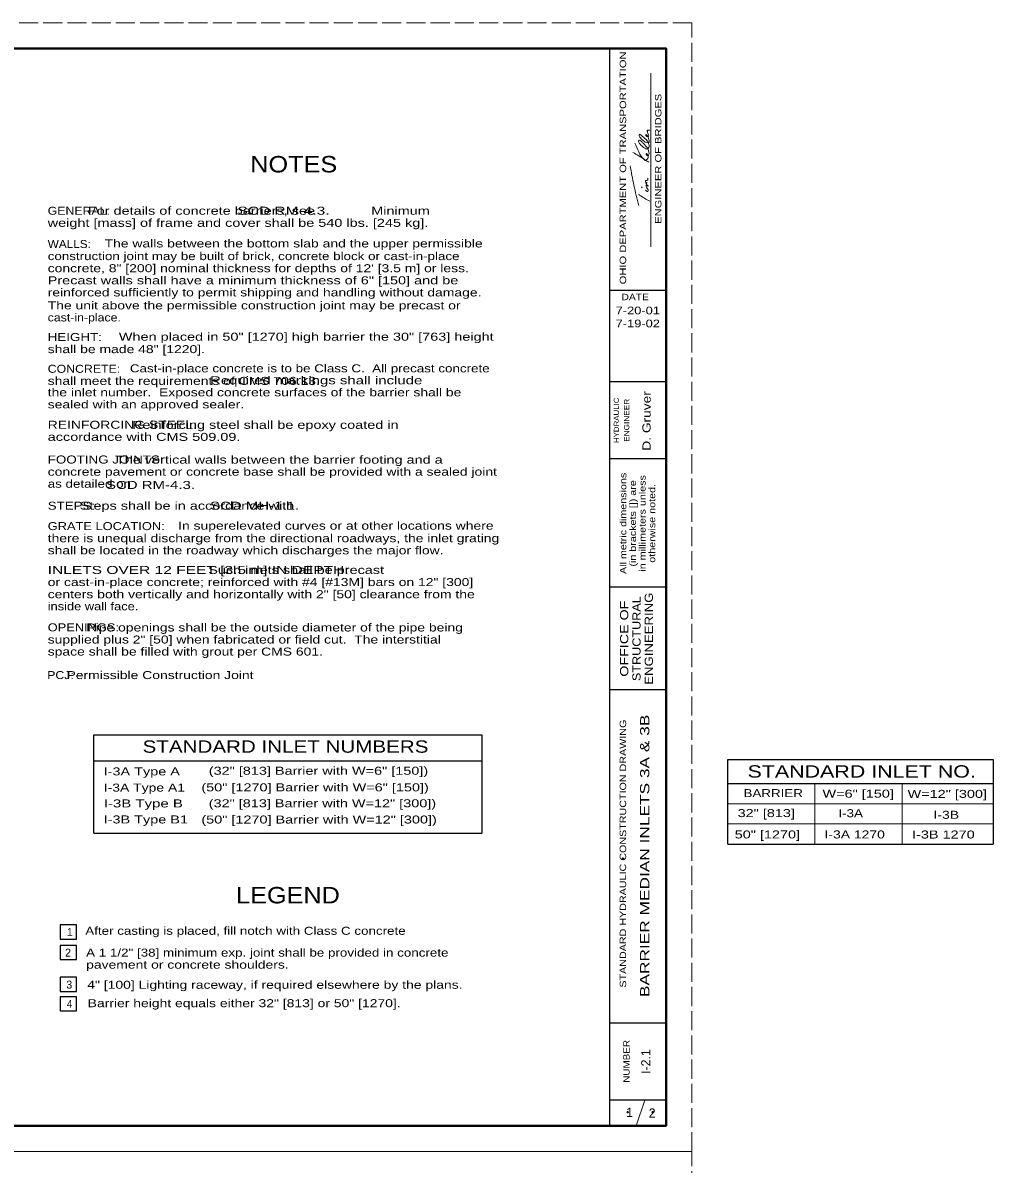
# Model space of a CAD drawing. Extents: x 1083.1 to 1123, y 697.4 to 741.4.
# Drawn here: x 1104.08 to 1123, y 719.1 to 741.35 of the extents above; entities that cross this region are included whole.
import ezdxf
from ezdxf.enums import TextEntityAlignment as Align

# ---------------------------------------------------------------- set-up
doc = ezdxf.new("R2010")
doc.units = 0
doc.header["$LTSCALE"] = 0.062
doc.header["$PDMODE"] = 32
doc.header["$PDSIZE"] = 0.031
doc.linetypes.add('LONG_DASHED', pattern=[7.5, 6, -1.5])
doc.layers.add('1', color=7, linetype='Continuous', lineweight=13)

msp = doc.modelspace()

# ---------------------------------------------------------------- linework, layer by layer
at = {"layer": '1', "lineweight": 25}
for p, q in [((1085.12642, 740.85408), (1116.62642, 740.85408)), ((1115.52642, 719.85408), (1115.52642, 740.85408)), ((1116.62642, 740.85408), (1116.62642, 719.85408)), ((1116.62642, 736.13825), (1115.52642, 736.13825)), ((1116.62642, 734.35408), (1115.52642, 734.35408)), ((1116.62642, 732.85408), (1115.52642, 732.85408)), ((1116.62642, 730.35408), (1115.52642, 730.35408)), ((1116.62642, 728.35408), (1115.52642, 728.35408)), ((1113.03458, 727.47617), (1113.03458, 725.559)), ((1105.465, 726.96483), (1113.03458, 726.96483)), ((1117.82975, 726.995), (1123.0025, 726.995)), ((1117.82975, 725.343), (1117.82975, 726.995)), ((1123.0025, 726.995), (1123.0025, 725.343)), ((1117.82975, 726.523), (1123.0025, 726.523)), ((1105.465, 725.559), (1113.03458, 725.559)), ((1117.82975, 725.343), (1123.0025, 725.343)), ((1116.62642, 721.85408), (1115.52642, 721.85408)), ((1116.62642, 720.35408), (1115.52642, 720.35408))]:
    msp.add_line(p, q, dxfattribs=at)
at = {"layer": '1'}
for p, q in [((1116.32517, 736.98508), (1116.32517, 740.37517)), ((1116.15767, 738.136), (1116.1475, 738.15525)), ((1119.52775, 726.523), (1119.52775, 725.343)), ((1121.22583, 726.523), (1121.22583, 725.343)), ((1117.82975, 726.12967), (1123.0025, 726.12967)), ((1117.82975, 725.73633), (1123.0025, 725.73633)), ((1116.04308, 719.85408), (1116.20975, 720.35408))]:
    msp.add_line(p, q, dxfattribs=at)
at = {"layer": '1', "linetype": 'LONG_DASHED'}
for points in [[(1083.12642, 719.35408), (1117.12642, 719.35408), (1117.12642, 741.35408), (1083.12642, 741.35408)], [(1083.12642, 697.35408), (1117.12642, 697.35408), (1117.12642, 719.35408), (1083.12642, 719.35408)]]:
    msp.add_lwpolyline(points, close=True, dxfattribs=at)
at = {"layer": '1', "lineweight": 25}
for points in [[(1116.62642, 719.85408), (1085.12642, 719.85408), (1085.12642, 740.85408)], [(1105.465, 725.559), (1105.465, 727.47617), (1113.03458, 727.47617)]]:
    msp.add_lwpolyline(points, dxfattribs=at)
at = {"layer": '1', "lineweight": 40}
msp.add_lwpolyline([(1085.12642, 740.85408), (1116.62642, 740.85408), (1116.62642, 719.85408), (1085.12642, 719.85408)], close=True, dxfattribs=at)
at = {"layer": '1', "lineweight": 25}
for points in [[(1104.81317, 723.76742), (1104.81317, 723.49208), (1105.1275, 723.49208), (1105.1275, 723.76742)], [(1104.81317, 723.36892), (1104.81317, 723.09342), (1105.1275, 723.09342), (1105.1275, 723.36892)], [(1104.81317, 722.74675), (1104.81317, 722.47125), (1105.1275, 722.47125), (1105.1275, 722.74675)], [(1104.81317, 722.36758), (1104.81317, 722.09225), (1105.1275, 722.09225), (1105.1275, 722.36758)]]:
    msp.add_lwpolyline(points, close=True, dxfattribs=at)
at = {"layer": '1'}
for points in [[(1116.01825, 739.01108), (1116.20142, 738.68275), (1116.21658, 738.67217), (1116.22675, 738.67217), (1116.25867, 738.69583), (1116.27375, 738.73), (1116.26875, 738.78125), (1116.25183, 738.80308), (1116.23833, 738.80308), (1116.23658, 738.79008), (1116.24675, 738.77492), (1116.26025, 738.7665), (1116.27533, 738.7665), (1116.2905, 738.78808), (1116.29392, 738.80742), (1116.28367, 738.86275), (1116.20142, 738.98317), (1116.15592, 739.02783), (1116.119, 739.06242), (1116.09383, 739.06458), (1116.09558, 739.026), (1116.12075, 738.98725), (1116.188, 738.92492), (1116.23008, 738.8995), (1116.26375, 738.895), (1116.28708, 738.921), (1116.29392, 738.95517), (1116.28883, 738.98092), (1116.25867, 739.05408), (1116.22842, 739.08608), (1116.16783, 739.1395), (1116.13917, 739.16533), (1116.10567, 739.18058), (1116.10225, 739.15258), (1116.11233, 739.12675), (1116.1695, 739.06683), (1116.24017, 739.01958), (1116.29217, 739.02192), (1116.2905, 739.07958), (1116.27867, 739.1225), (1116.26533, 739.14825), (1116.25517, 739.159), (1116.23175, 739.174), (1116.2335, 739.15692), (1116.26875, 739.13542), (1116.28367, 739.14617), (1116.27058, 739.19983), (1116.262, 739.22775), (1116.25867, 739.24042), (1116.25867, 739.25325), (1116.25867, 739.26192), (1116.28367, 739.25975), (1116.30908, 739.25975)], [(1115.97942, 738.82883), (1116.20317, 738.69133), (1116.28883, 738.63567)], [(1116.09567, 737.79183), (1115.997, 738.18708), (1115.92575, 738.56942)], [(1116.22675, 738.09075), (1116.235, 738.08008), (1116.27217, 738.06717), (1116.27692, 738.09958), (1116.25183, 738.136), (1116.23658, 738.17225), (1116.23658, 738.1915), (1116.25183, 738.18525), (1116.262, 738.17442), (1116.27217, 738.17008), (1116.2485, 738.20225), (1116.23658, 738.21725), (1116.2335, 738.23458), (1116.25692, 738.228), (1116.2485, 738.23667), (1116.22333, 738.2645), (1116.2335, 738.27967), (1116.25025, 738.28167), (1116.25867, 738.27967), (1116.26875, 738.301), (1116.262, 738.32892)], [(1116.31083, 737.87625), (1116.10567, 737.99625), (1116.09008, 738.00667)]]:
    msp.add_spline(points, degree=3, dxfattribs=at)
for p in [(1115.78383, 725.06008), (1116.21667, 725.06742), (1115.8745, 720.11783), (1116.36292, 720.11683)]:
    msp.add_point(p, dxfattribs=at)

# ---------------------------------------------------------------- texts
for s, height, width, p in [('OHIO DEPARTMENT OF TRANSPORTATION', 0.125, 1.3, (1115.84633, 738.52633)), ('ENGINEER OF BRIDGES', 0.125, 1.3, (1116.53467, 738.70312)), ('HYDRAULIC', 0.1, 1.15, (1115.7055, 733.60517)), ('D. Gruver', 0.16, 1.25, (1116.32408, 733.59333)), ('ENGINEER', 0.1, 1.2, (1115.90642, 733.60521)), ('All metric dimensions', 0.125, 1.25, (1115.85025, 731.59617)), ('in millimeters unless', 0.125, 1.25, (1116.22525, 731.59621)), ('(in brackets []) are', 0.125, 1.25, (1116.03775, 731.59617)), ('otherwise noted.', 0.125, 1.25, (1116.41275, 731.59617)), ('OFFICE OF', 0.16, 1.3, (1115.88817, 729.34854)), ('STRUCTURAL', 0.16, 1.15, (1116.12817, 729.34854)), ('ENGINEERING', 0.16, 1.2, (1116.36817, 729.34862)), ('BARRIER MEDIAN INLETS 3A & 3B', 0.18, 1.4, (1116.29842, 725.11421)), ('STANDARD HYDRAULIC CONSTRUCTION DRAWING', 0.125, 1.25, (1115.84633, 725.15812)), ('NUMBER', 0.125, 1.15, (1115.91342, 721.10817))]:
    msp.add_text(s, height=height, rotation=90, dxfattribs=dict(at, width=width)).set_placement(p, align=Align.CENTER)
for s, height, width, p in [('NOTES', 0.32, 1.15, (1108.51775, 738.438)), ('GENERAL:', 0.156, 1.15, (1104.56858, 737.61292)), ('          For details of concrete barriers, see              Minimum', 0.156, 1.35, (1104.56858, 737.61292)), ('                                            SCD RM-4.3.', 0.156, 1.45, (1104.56858, 737.61292)), ('weight [mass] of frame and cover shall be 540 lbs. [245 kg].', 0.156, 1.35, (1104.56858, 737.37692)), ('WALLS:', 0.156, 1.1, (1104.56858, 736.96433)), ('The walls between the bottom slab and the upper permissible', 0.156, 1.3, (1105.67717, 736.97533)), ('construction joint may be built of brick, concrete block or cast-in-place ', 0.156, 1.25, (1104.56858, 736.72833)), ('concrete, 8" [200] nominal thickness for depths of 12\' [3.5 m] or less. ', 0.156, 1.3, (1104.56858, 736.49233)), ('Precast walls shall have a minimum thickness of 6" [150] and be', 0.156, 1.35, (1104.56858, 736.25633)), ('reinforced sufficiently to permit shipping and handling without damage.', 0.156, 1.3, (1104.56858, 736.02033)), ('The unit above the permissible construction joint may be precast or', 0.156, 1.3, (1104.56858, 735.7675)), ('cast-in-place.', 0.156, 1.15, (1104.56858, 735.53283)), ('HEIGHT:', 0.156, 1.25, (1104.56858, 735.15058)), ('When placed in 50" [1270] high barrier the 30" [763] height ', 0.156, 1.35, (1105.95508, 735.15717)), ('shall be made 48" [1220].', 0.156, 1.3, (1104.56858, 734.91458)), ('Cast-in-place concrete is to be Class C.  All precast concrete', 0.156, 1.25, (1106.17058, 734.5405)), ('CONCRETE:', 0.156, 1.15, (1104.56858, 734.53167)), ('shall meet the requirements of CMS 706.13.', 0.156, 1.3, (1104.56858, 734.29567)), ('                                       Required markings shall include', 0.156, 1.4, (1104.56858, 734.30758)), ('the inlet number.  Exposed concrete surfaces of the barrier shall be', 0.156, 1.3, (1104.56858, 734.07292)), ('sealed with an approved sealer.', 0.156, 1.3, (1104.56858, 733.83825)), ('REINFORCING STEEL:', 0.156, 1.3, (1104.56858, 733.44042)), ('                     Reinforcing steel shall be epoxy coated in', 0.156, 1.35, (1104.56858, 733.43908)), ('accordance with CMS 509.09.', 0.156, 1.35, (1104.56858, 733.20442)), ('FOOTING JOINTS:', 0.156, 1.25, (1104.56858, 732.763)), ('                 The vertical walls between the barrier footing and a', 0.156, 1.35, (1104.56858, 732.76033)), ('concrete pavement or concrete base shall be provided with a sealed joint', 0.156, 1.3, (1104.56858, 732.52567)), ('as detailed on', 0.156, 1.25, (1104.56858, 732.291)), ('              SCD RM-4.3.', 0.156, 1.4, (1104.56858, 732.26717)), ('        Steps shall be in accordance with ', 0.156, 1.35, (1104.56858, 731.86267)), ('STEPS:', 0.156, 1.25, (1104.56858, 731.86267)), ('                                       SCD MH-1.1.', 0.156, 1.4, (1104.56858, 731.86267)), ('GRATE LOCATION:', 0.156, 1.2, (1104.56858, 731.46492)), ('In superelevated curves or at other locations where', 0.156, 1.3, (1107.11133, 731.47375)), ('there is unequal discharge from the directional roadways, the inlet grating', 0.156, 1.3, (1104.56858, 731.22892)), ('shall be located in the roadway which discharges the major flow.', 0.156, 1.3, (1104.56858, 730.99292)), ('INLETS OVER 12 FEET [3.5 m] IN DEPTH:', 0.156, 1.45, (1104.56858, 730.61)), ('                                        Such inlets shall be precast', 0.156, 1.35, (1104.56858, 730.61)), ('or cast-in-place concrete; reinforced with #4 [#13M] bars on 12" [300]', 0.156, 1.3, (1104.56858, 730.374)), ('centers both vertically and horizontally with 2" [50] clearance from the', 0.156, 1.3, (1104.56858, 730.13667)), ('inside wall face.', 0.156, 1.2, (1104.56858, 729.902)), ('OPENINGS:', 0.156, 1.2, (1104.56858, 729.49108)), ('          Pipe openings shall be the outside diameter of the pipe being', 0.156, 1.3, (1104.56858, 729.48842)), ('supplied plus 2" [50] when fabricated or field cut.  The interstitial', 0.156, 1.3, (1104.56858, 729.25375)), ('space shall be filled with grout per CMS 601.', 0.156, 1.3, (1104.56858, 729.01908)), ('PCJ:', 0.156, 1.15, (1104.55792, 728.56075)), ('     Permissible Construction Joint', 0.156, 1.3, (1104.55792, 728.56075)), ('STANDARD INLET NUMBERS', 0.24, 1.25, (1106.41908, 727.12517)), ('I-3A Type A', 0.156, 1.35, (1105.65925, 726.68292)), ('(32" [813] Barrier with W=6" [150])', 0.156, 1.35, (1107.70925, 726.69575)), ('STANDARD INLET NO.', 0.24, 1.3, (1118.21358, 726.64058)), ('I-3A Type A1', 0.156, 1.3, (1105.66208, 726.367)), ('(50" [1270] Barrier with W=6" [150])', 0.156, 1.35, (1107.56458, 726.372)), ('BARRIER', 0.156, 1.25, (1118.13467, 726.2595)), ('W=6" [150]', 0.156, 1.35, (1119.67492, 726.24917)), ('W=12" [300]', 0.156, 1.35, (1121.33367, 726.24458)), ('I-3B Type B', 0.156, 1.4, (1105.66217, 726.05875)), ('(32" [813] Barrier with W=12" [300])', 0.156, 1.35, (1107.70792, 726.0615)), ('32" [813]', 0.156, 1.35, (1118.0195, 725.87033)), ('I-3A', 0.156, 1.25, (1119.985, 725.86775)), ('I-3B Type B1', 0.156, 1.35, (1105.6595, 725.74642)), ('(50" [1270] Barrier with W=12" [300])', 0.156, 1.35, (1107.56433, 725.74483)), ('I-3B', 0.156, 1.3, (1121.83983, 725.83692)), ('50" [1270]', 0.156, 1.35, (1117.963, 725.45392)), ('I-3A 1270', 0.156, 1.3, (1119.71467, 725.45408)), ('I-3B 1270', 0.156, 1.35, (1121.421, 725.45283)), ('LEGEND', 0.32, 1.15, (1108.24108, 724.18817)), ('After casting is placed, fill notch with Class C concrete', 0.156, 1.25, (1105.30117, 723.57567)), ('A 1 1/2" [38] minimum exp. joint shall be provided in concrete', 0.156, 1.25, (1105.31775, 723.15017)), ('pavement or concrete shoulders.', 0.156, 1.3, (1105.31775, 722.9155)), ('4" [100] Lighting raceway, if required elsewhere by the plans.', 0.156, 1.3, (1105.33908, 722.5235)), ('4', 0.156, 0.9, (1104.94175, 722.15025)), ('Barrier height equals either 32" [813] or 50" [1270].', 0.156, 1.3, (1105.34767, 722.16458))]:
    msp.add_text(s, height=height, dxfattribs=dict(at, width=width)).set_placement(p)
for s, height, width, p in [('DATE', 0.125, 1.2, (1116.02312, 735.94683)), ('7-20-01', 0.15, 1.25, (1116.07346, 735.67133)), ('7-19-02', 0.15, 1.25, (1116.07346, 735.41825))]:
    msp.add_text(s, height=height, dxfattribs=dict(at, width=width)).set_placement(p, align=Align.CENTER)
for s, p in [('1', (1104.94175, 723.55)), ('2', (1104.90642, 723.14992)), ('3', (1104.9305, 722.52683))]:
    msp.add_text(s, height=0.156, dxfattribs=at).set_placement(p)
msp.add_text('I-2.1', height=0.18, rotation=90, dxfattribs=at).set_placement((1116.32058, 721.10442), align=Align.CENTER)
for s, p in [('1', (1115.91427, 720.02417)), ('2', (1116.35371, 720.01158))]:
    msp.add_text(s, height=0.18, dxfattribs=at).set_placement(p, align=Align.CENTER)

doc.saveas('drawing.dxf')
